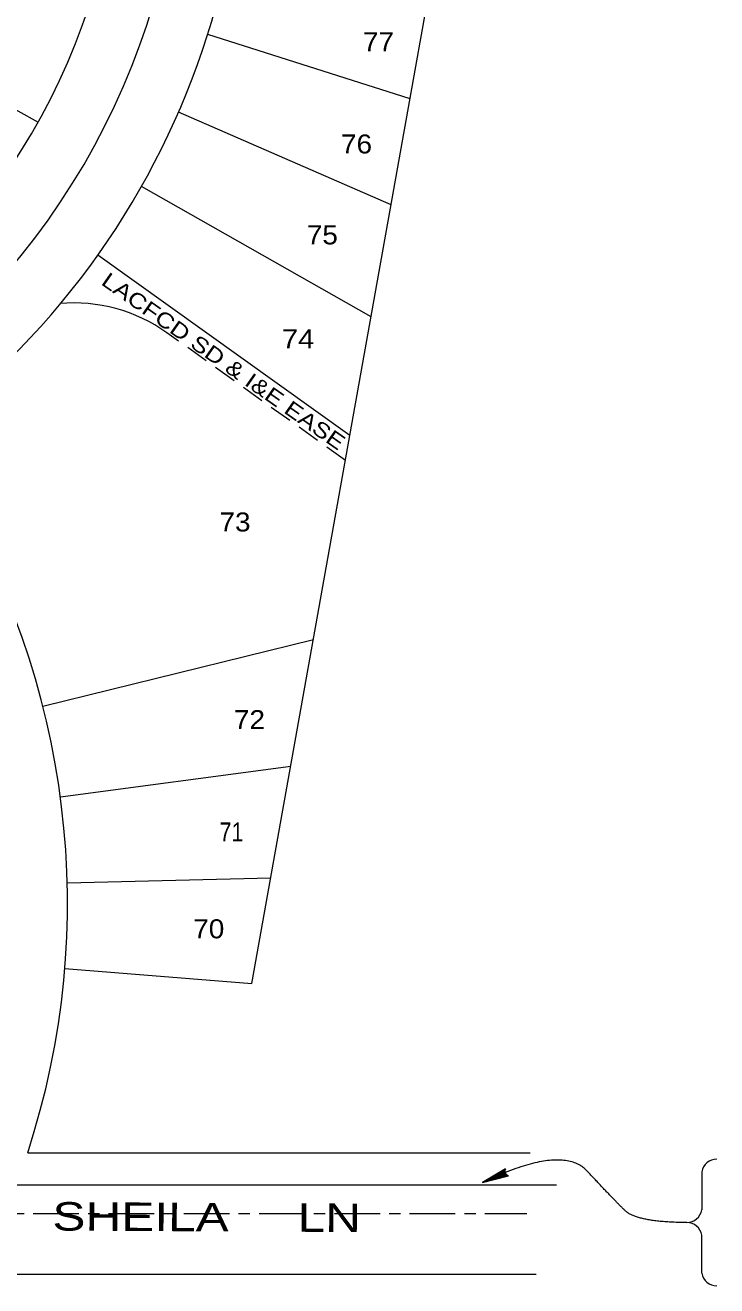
# Model space of a CAD drawing. Extents: x 6387474 to 6390971, y 1972046 to 1973920.
# Drawn here: x 6389640 to 6390004, y 1972116 to 1972779 of the extents above; entities that cross this region are included whole.
import ezdxf

# ---------------------------------------------------------------- set-up
doc = ezdxf.new("R2010")
doc.units = 0
doc.header["$LTSCALE"] = 4
doc.linetypes.add('LONG_DASH_SHORT_DASH', pattern=[9.9, 6, -1.2, 1.5, -1.2])
doc.linetypes.add('MEDIUM_DASHED', pattern=[4.5, 3, -1.5])
for name, color, linetype, lineweight in [('1', 7, 'Continuous', 13), ('2', 7, 'LONG_DASH_SHORT_DASH', 13), ('3', 7, 'Continuous', 13), ('4', 7, 'Continuous', 13), ('5', 7, 'MEDIUM_DASHED', 13), ('8', 7, 'Continuous', 13)]:
    doc.layers.add(name, color=color, linetype=linetype, lineweight=lineweight)
doc.layers.add('7', color=7, linetype='Continuous')

msp = doc.modelspace()

# ---------------------------------------------------------------- hatches: boundary and pattern name
at = {"layer": '8'}
for points in [[(6389880.456, 1972170.211), (6389892.372, 1972176.92), (6389892.605, 1972177.449)], [(6389880.456, 1972170.211), (6389892.266, 1972176.351), (6389892.372, 1972176.92)], [(6389880.456, 1972170.211), (6389892.293, 1972175.774), (6389892.266, 1972176.351)], [(6389892.453, 1972175.218), (6389892.293, 1972175.774), (6389880.456, 1972170.211)], [(6389892.736, 1972174.714), (6389892.453, 1972175.218), (6389880.456, 1972170.211)], [(6389893.127, 1972174.288), (6389892.736, 1972174.714), (6389880.456, 1972170.211)], [(6389893.606, 1972173.963), (6389893.127, 1972174.288), (6389880.456, 1972170.211)], [(6389894.146, 1972173.757), (6389893.606, 1972173.963), (6389880.456, 1972170.211)]]:
    msp.add_hatch(color=256, dxfattribs=at).paths.add_polyline_path(points)

# ---------------------------------------------------------------- linework, layer by layer
at = {"layer": '1'}
for p, q in [((6389759.246, 1972274.953), (6389876.154, 1972929.685)), ((6389660.801, 1972282.98), (6389759.246, 1972274.953))]:
    msp.add_line(p, q, dxfattribs=at)
at = {"layer": '2'}
msp.add_line((6389050.214, 1972153.984), (6389903.778, 1972153.984), dxfattribs=at)
at = {"layer": '2', "linetype": 'Continuous'}
msp.add_arc((6389335.562, 1972901.304), 388, 270.34667, 18.92364, dxfattribs=at)
at = {"layer": '3'}
for p, q in [((6389538.594, 1972788.433), (6389646.715, 1972728.329)), ((6389842.398, 1972740.642), (6389735.969, 1972774.517)), ((6389832.423, 1972684.775), (6389720.644, 1972733.637)), ((6389821.899, 1972625.837), (6389701.085, 1972694.438)), ((6389810.751, 1972563.404), (6389678.103, 1972658.269)), ((6389791.556, 1972455.904), (6389649.298, 1972420.824)), ((6389779.641, 1972389.174), (6389658.499, 1972373.03)), ((6389769.17, 1972330.531), (6389662.065, 1972327.85))]:
    msp.add_line(p, q, dxfattribs=at)
at = {"layer": '4'}
for p, q in [((6389641.252, 1972185.984), (6389905.571, 1972185.984)), ((6389614.286, 1972121.983), (6389908.78, 1972121.983))]:
    msp.add_line(p, q, dxfattribs=at)
for centre, radius, start, end in [((6389335.562, 1972901.304), 420, 307.91924, 18.92365), ((6389335.562, 1972901.304), 356, 270.34667, 18.92365), ((6389240.198, 1972317.283), 422, 341.87222, 31.95472)]:
    msp.add_arc(centre, radius, start, end, dxfattribs=at)
at = {"layer": '5'}
msp.add_line((6389808.415, 1972550.321), (6389714.468, 1972617.508), dxfattribs=at)
at = {"layer": '5', "linetype": 'Continuous'}
msp.add_arc((6389665.604, 1972549.183), 84, 54.42917, 95.08871, dxfattribs=at)
at = {"layer": '8'}
for p, q in [((6389995.91, 1972175.873), (6389995.91, 1972155.893)), ((6389050.214, 1972169.009), (6389919.45, 1972169.009)), ((6389995.91, 1972122.587), (6389995.91, 1972142.567))]:
    msp.add_line(p, q, dxfattribs=at)
for points in [[(6389938.553, 1972173.171), (6389938.083, 1972173.676), (6389937.609, 1972174.187), (6389937.13, 1972174.703), (6389936.647, 1972175.224), (6389936.159, 1972175.751), (6389935.666, 1972176.283), (6389935.16, 1972176.806), (6389934.634, 1972177.305), (6389934.088, 1972177.779), (6389933.52, 1972178.228), (6389932.932, 1972178.653), (6389932.324, 1972179.053), (6389931.694, 1972179.429), (6389931.045, 1972179.78), (6389930.374, 1972180.107), (6389929.683, 1972180.409), (6389928.971, 1972180.687), (6389928.239, 1972180.94), (6389927.486, 1972181.169), (6389926.713, 1972181.373), (6389925.918, 1972181.553), (6389925.104, 1972181.708), (6389924.268, 1972181.838), (6389923.412, 1972181.945), (6389922.535, 1972182.026), (6389921.638, 1972182.083), (6389920.72, 1972182.116), (6389919.781, 1972182.124), (6389918.822, 1972182.107), (6389917.842, 1972182.066), (6389916.842, 1972182.001), (6389915.821, 1972181.911), (6389914.779, 1972181.796), (6389913.717, 1972181.657), (6389912.634, 1972181.493), (6389911.53, 1972181.305), (6389910.406, 1972181.092), (6389909.261, 1972180.855), (6389908.096, 1972180.593), (6389906.91, 1972180.307), (6389905.703, 1972179.996), (6389904.476, 1972179.661), (6389903.228, 1972179.301), (6389901.959, 1972178.917), (6389900.67, 1972178.508), (6389899.36, 1972178.075), (6389898.03, 1972177.617), (6389896.679, 1972177.135), (6389895.307, 1972176.628), (6389893.915, 1972176.096), (6389892.502, 1972175.54), (6389891.068, 1972174.96), (6389889.614, 1972174.355), (6389888.139, 1972173.725), (6389886.644, 1972173.071), (6389885.128, 1972172.393), (6389883.591, 1972171.69), (6389882.034, 1972170.962), (6389880.456, 1972170.21)], [(6389892.605, 1972177.449), (6389880.456, 1972170.211), (6389894.146, 1972173.758)], [(6389956.449, 1972154.73), (6389956.153, 1972154.957), (6389955.871, 1972155.188), (6389955.602, 1972155.424), (6389955.348, 1972155.665), (6389955.098, 1972155.911), (6389954.843, 1972156.162), (6389954.584, 1972156.418), (6389954.32, 1972156.68), (6389954.051, 1972156.948), (6389953.778, 1972157.221), (6389953.5, 1972157.5), (6389953.218, 1972157.784), (6389952.93, 1972158.074), (6389952.638, 1972158.369), (6389952.342, 1972158.67), (6389952.04, 1972158.976), (6389951.734, 1972159.288), (6389951.424, 1972159.605), (6389951.109, 1972159.928), (6389950.789, 1972160.257), (6389950.464, 1972160.591), (6389950.135, 1972160.93), (6389949.801, 1972161.275), (6389949.462, 1972161.625), (6389949.119, 1972161.981), (6389948.771, 1972162.343), (6389948.418, 1972162.71), (6389948.061, 1972163.082), (6389947.699, 1972163.46), (6389947.332, 1972163.844), (6389946.961, 1972164.233), (6389946.585, 1972164.627), (6389946.204, 1972165.027), (6389945.818, 1972165.433), (6389945.428, 1972165.844), (6389945.034, 1972166.26), (6389944.634, 1972166.683), (6389944.23, 1972167.11), (6389943.822, 1972167.543), (6389943.408, 1972167.982), (6389942.99, 1972168.426), (6389942.567, 1972168.876), (6389942.14, 1972169.331), (6389941.708, 1972169.792), (6389941.271, 1972170.258), (6389940.83, 1972170.73), (6389940.384, 1972171.207), (6389939.933, 1972171.69), (6389939.477, 1972172.178), (6389939.017, 1972172.672), (6389938.553, 1972173.171)], [(6389988.024, 1972149.229), (6389987.045, 1972149.231), (6389986.081, 1972149.238), (6389985.13, 1972149.25), (6389984.193, 1972149.266), (6389983.27, 1972149.286), (6389982.361, 1972149.312), (6389981.466, 1972149.341), (6389980.585, 1972149.376), (6389979.718, 1972149.415), (6389978.865, 1972149.458), (6389978.026, 1972149.506), (6389977.2, 1972149.559), (6389976.389, 1972149.616), (6389975.591, 1972149.678), (6389974.808, 1972149.745), (6389974.038, 1972149.816), (6389973.282, 1972149.891), (6389972.54, 1972149.971), (6389971.812, 1972150.056), (6389971.098, 1972150.146), (6389970.398, 1972150.24), (6389969.712, 1972150.338), (6389969.04, 1972150.441), (6389968.382, 1972150.549), (6389967.737, 1972150.661), (6389967.107, 1972150.778), (6389966.49, 1972150.899), (6389965.888, 1972151.025), (6389965.299, 1972151.156), (6389964.724, 1972151.291), (6389964.163, 1972151.431), (6389963.617, 1972151.575), (6389963.084, 1972151.724), (6389962.564, 1972151.878), (6389962.059, 1972152.036), (6389961.568, 1972152.198), (6389961.091, 1972152.366), (6389960.627, 1972152.538), (6389960.178, 1972152.714), (6389959.742, 1972152.895), (6389959.321, 1972153.081), (6389958.913, 1972153.271), (6389958.519, 1972153.465), (6389958.14, 1972153.665), (6389957.774, 1972153.869), (6389957.422, 1972154.077), (6389957.084, 1972154.29), (6389956.759, 1972154.508), (6389956.449, 1972154.73)]]:
    msp.add_lwpolyline(points, dxfattribs=at)
for points in [[(6389880.456, 1972170.211), (6389892.372, 1972176.92), (6389892.605, 1972177.449)], [(6389880.456, 1972170.211), (6389892.266, 1972176.351), (6389892.372, 1972176.92)], [(6389880.456, 1972170.211), (6389892.293, 1972175.774), (6389892.266, 1972176.351)], [(6389892.453, 1972175.218), (6389892.293, 1972175.774), (6389880.456, 1972170.211)], [(6389892.736, 1972174.714), (6389892.453, 1972175.218), (6389880.456, 1972170.211)], [(6389893.127, 1972174.288), (6389892.736, 1972174.714), (6389880.456, 1972170.211)], [(6389893.606, 1972173.963), (6389893.127, 1972174.288), (6389880.456, 1972170.211)], [(6389894.146, 1972173.757), (6389893.606, 1972173.963), (6389880.456, 1972170.211)]]:
    msp.add_lwpolyline(points, close=True, dxfattribs=at)
for centre, radius, start, end in [((6389894.76, 1972176.181), 2.5, 149.5258, 255.78601), ((6390003.799, 1972174.536), 8, 90, 170.38048), ((6389988.024, 1972157.229), 8, 270, 350.38048), ((6389988.024, 1972141.229), 8, 9.61952, 90), ((6390003.799, 1972123.923), 8, 189.61952, 270)]:
    msp.add_arc(centre, radius, start, end, dxfattribs=at)

# ---------------------------------------------------------------- texts
at = {"layer": '2', "width": 1.3}
msp.add_text('SHEILA     LN', height=15, rotation=359.712, dxfattribs=at).set_placement((6389654.232, 1972144.988))
at = {"layer": '5', "width": 1.25}
msp.add_text('LACFCD SD & I&E EASE', height=8, rotation=324.926, dxfattribs=at).set_placement((6389679.361, 1972643.24))
at = {"layer": '7'}
for s, width, p in [('77', 1.1, (6389817.656, 1972765.664)), ('76', 1.1, (6389806.091, 1972711.859)), ('75', 1.1, (6389788.094, 1972664.009)), ('74', 1.15, (6389774.964, 1972609.262)), ('73', 1.1, (6389742.139, 1972512.907)), ('72', 1.1, (6389749.738, 1972408.888)), ('71', 0.85, (6389742.139, 1972349.761)), ('70', 1.1, (6389728.343, 1972298.793))]:
    msp.add_text(s, height=10, dxfattribs=dict(at, width=width)).set_placement(p)

doc.saveas('drawing.dxf')
